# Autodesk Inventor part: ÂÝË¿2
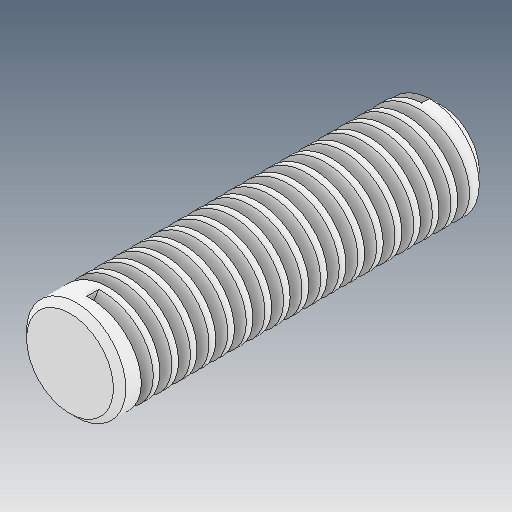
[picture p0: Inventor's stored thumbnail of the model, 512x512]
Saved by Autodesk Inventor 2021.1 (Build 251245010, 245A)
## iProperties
Created: 2021-05
Part Number: ÂÝË¿2
Material: Ogólny
Document SubType Name: Modeling
Designer: user
Density: 1 g/cm^3
Appearance: Domyślna
Author: user
Revision Number: ÈÎºÎ
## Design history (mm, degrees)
feature "ÊäÈë1"
node "Bryła1"
